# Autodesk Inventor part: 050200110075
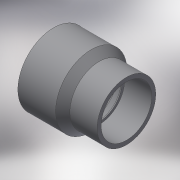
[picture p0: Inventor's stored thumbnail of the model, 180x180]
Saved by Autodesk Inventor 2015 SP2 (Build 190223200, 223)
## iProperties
Created: 2017-10
Part Number: 050200110075
Material: Generic
Description: PLASSON REDUCING SOCKET M.F.110(90)75 CEMENTED
Document SubType Name: Modeling
Designer: KIM
Density: 1 g/cm^3
Appearance: Default
Author: KIM
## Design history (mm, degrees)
derived "050200.ipt"
feature "Solid1::050200.ipt"
tag "TaggingFeature1"
body "Solid1"
other parameters: "d0" = 133, "d1" = 61, "d2" = 44, "d3" = 51, "d4" = 75, "d8" = 67.5, "d9" = 3.43024, "d12" = 0.9, "d_1" = 75, "L_" = 61, "l_" = 51, "l_1" = 44, "H_" = 133, "d11" = 3.43024
